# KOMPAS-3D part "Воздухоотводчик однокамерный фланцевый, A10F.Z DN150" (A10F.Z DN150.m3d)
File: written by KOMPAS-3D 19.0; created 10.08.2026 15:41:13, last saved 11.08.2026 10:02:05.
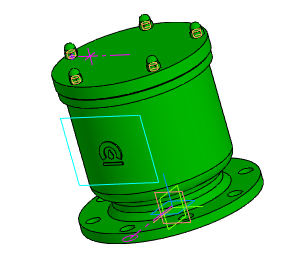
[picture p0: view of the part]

Document properties: Автор: Энергия; Полное имя файла: Z:\3.Личные\kachalov\001_3d для проектировщиков\x.x Тип A10F.Z Воздухоотводчик однокамерный фланцевый\A10F.Z DN150.m3d

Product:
- Part/product: Воздухоотводчик однокамерный фланцевый  | designation A10F.Z DN150
    Масса: 44.0992
  - Component [standard]: Гайка М12-6H (S18) ГОСТ 11860-85  | qty 5  | Масса: 0.02606; Раздел спецификации: Стандартные изделия; Рассекать на разрезах: no; source file: C:\Program Files\ASCON\KOMPAS-3D v19\Libs\PARTLib\DATA\vault\Methods\Kompas\3D\PLib_Blind_Nut_type1_900.m3d
  - Body: Тело 1
      Масса: 44.0471

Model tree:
1. Эскиз:1
2. Элемент вращения:1
     Угол 1 = 360
3. Скругление:1  (with: Элемент вращения:1)
     Радиус = 10
4. Фаска:1  (with: Элемент вращения:1)
     Угол = 45; Длина 1 = 10; Длина 2 = 10
5. Эскиз:2  (with: Элемент вращения:1)
6. Точка:1
     Y = -105; Z = 248; Координата Y = -105; Координата Z = 248
7. Массив по концентрической сетке:1  (with: Элемент вращения:1)  (5 pattern instances)
     Шаг 2 = 360
8. Эскиз:3  (with: Элемент вращения:1)
9. Элемент выдавливания:1  (with: Элемент вращения:1, Массив по концентрической сетке:1, Эскиз:3)  (8 pattern instances)
     Расстояние 2 = 16; N 1 = 1; Шаг 1 = 10; Шаг 2 = 360; Номер 1 = 1
10. Касательная плоскость:1  (with: Элемент вращения:1)
11. Эскиз:4
12. Элемент выдавливания:2  (with: Элемент вращения:1)  (labels: Фаска наружная:1)
     Расстояние 1 = 1; Ориентация = 2

Expressions: Dn/2; D2/2; D/2; B/2; H/2; D1/2-10; D1-30
Referenced files in C:\Program Files\ASCON\KOMPAS-3D v19\Libs\PARTLib\DATA\vault\Methods\Kompas\3D\: PLib_Blind_Nut_type1_900.m3d
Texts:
  A10F.Z DN150
  Гайка М12-6H (S18) ГОСТ 11860-85 (1)
  foc1
  foc2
